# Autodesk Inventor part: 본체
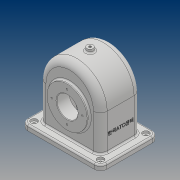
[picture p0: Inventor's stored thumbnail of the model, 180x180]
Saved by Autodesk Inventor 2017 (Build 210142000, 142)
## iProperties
Part Number: 본체
Material: 일반
Document SubType Name: Modeling
Designer: 20
Density: 1 g/cm^3
Appearance: 기본값
Author: 20
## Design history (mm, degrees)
sketch "스케치8"
  geometry: L1 (58, 0)-(58, -78); L2 (58, -78)-(-58, -78); L3 (-58, -78)-(-58, 0); A1 r 58 centre (0, 0) between (58, 0) and (-58, 0); 1 further point
  constraints: 6 end point, 2 coincident, 2 point on circle, 2 tangent, 2 vertical, 1 centre point, 1 horizontal
  dimensions: "d35" = 116 diameter of A1; "d44" = 78 distance from line of L2 point (0, 0)
extrude "돌출4" new body sketch "스케치8" stored distance "d38" = 77; taper "d39" = 0 deg
sketch "스케치11"
  geometry: L1 (-58, -78)-(58, -78) reference; C1 r 38 at (0, -13); 1 further point
  constraints: 1 centre point, 1 vertical alignment
  dimensions: "d45" = 76 diameter of C1; "d46" = 65 distance from line of L1 C1.centre
extrude "돌출5" join sketch "스케치11" distance "d47" = 5; taper "d48" = 0 deg
sketch "스케치12"
  geometry: L1 (58, 78)-(-58, 78) reference; C1 r 38 at (0, 13); 1 further point
  constraints: 1 centre point, 1 vertical alignment
  dimensions: "d49" = 76 diameter of C1; "d50" = 65 distance from line of L1 C1.centre
extrude "돌출6" join sketch "스케치12" distance "d51" = 10; taper "d52" = 0 deg
sketch "스케치14"
  geometry: L1 (52, 0)-(52, -78); L2 (-52, 0)-(-52, -78); L3 (52, -78)-(-52, -78); A1 r 52 centre (0, 0) between (52, 0) and (-52, 0); 1 further point
  constraints: 6 end point, 2 point on circle, 2 tangent, 2 vertical, 1 centre point, 1 coincident, 1 horizontal
  dimensions: "d62" = 104 diameter of A1; "d63" = 78 distance from line of L3 point (0, 0)
extrude "돌출7" cut sketch "스케치14" stored distance "d64" = 67; taper "d65" = 0 deg
node "작업 평면3"
sketch "스케치18"
  geometry: L1 (-52, -65)-(52, -65) reference; C1 r 28 at (0, 0); 1 further point
  constraints: 1 centre point, 1 vertical alignment
  dimensions: "d72" = 56 diameter of C1; "d73" = 65 distance from line of L1 C1.centre
extrude "돌출9" join sketch "스케치18" distance "d74" = 14; taper "d75" = 40 deg
sketch "스케치19"
  geometry: C1 r 38 at (0, 0) reference; C2 r 20 at (0, 0); 1 further point
  constraints: 1 centre point, 1 coincident
  dimensions: "d76" = 40 diameter of C2
extrude "돌출10" cut sketch "스케치19" stored distance "d77" = 67; taper "d78" = 0 deg
sketch "스케치20"
  geometry: L1 (-17, -93.5)-(133, -93.5); L2 (133, -93.5)-(133, 16.5); L3 (133, 16.5)-(-17, 16.5); L4 (-17, 16.5)-(-17, -93.5); L5 (-17, -93.5)-(133, 16.5); L6 (133, -93.5)-(-17, 16.5); L7 (0, 0)-(0, -77) reference; L8 (116, -77)-(0, -77) reference; L9 (116, 0)-(116, -77) reference; L10 (0, 0)-(116, 0) reference; 1 further point
  constraints: 12 end point, 2 midpoint, 2 parallel, 1 horizontal, 1 perpendicular
  dimensions: "d79" = 150 distance of L3.end L2.end; "d80" = 110 distance of L2.end L1.end
extrude "돌출11" join sketch "스케치20" distance "d81" = 10; taper "d82" = 0 deg
fillet "모깎기2" dims "d83" = 12
hole "구멍1" diameter "d86" = 5; stored, may be unused: countersink angle "d90" = 90 deg, drill point angle "d92" = 118 deg; dims "d84" = 10, "d85" = 10, "d87" = 6, "d88" = 12, "d89" = 4, "d91" = 8
hole "구멍2" diameter "d95" = 5; stored, may be unused: countersink angle "d99" = 90 deg, drill point angle "d101" = 118 deg; dims "d93" = 10, "d94" = 10, "d96" = 6, "d97" = 12, "d98" = 4, "d100" = 8
hole "구멍3" diameter "d104" = 5; stored, may be unused: countersink angle "d108" = 90 deg, drill point angle "d110" = 118 deg; dims "d102" = 10, "d103" = 10, "d105" = 6, "d106" = 12, "d107" = 4, "d109" = 8
hole "구멍4" diameter "d113" = 5; stored, may be unused: countersink angle "d117" = 90 deg, drill point angle "d119" = 118 deg; dims "d111" = 10, "d112" = 10, "d114" = 6, "d115" = 12, "d116" = 4, "d118" = 8
fillet "모깎기4" dims "d121" = 13
fillet "모깎기5" dims "d122" = 8
fillet "모깎기6" dims "d123" = 3
fillet "모깎기7" dims "d124" = 3
chamfer "모따기1" distance "d125" = 1; stored, may be unused: second distance "d126" = 2, angle "d127" = 45 deg
node "작업 평면4"
sketch "스케치22"
  geometry: L1 (138, -12)-(138, -98) reference; L2 (126, -110)-(0, -110) reference; C1 r 6 at (63, -55); 1 further point
  constraints: 1 centre point
  dimensions: "d131" = 12 diameter of C1; "d132" = 55 distance from line of L2 C1.centre; "d133" = 75 distance from line of L1 C1.centre
extrude "돌출12" join sketch "스케치22" stored distance "d134" = 10; taper "d135" = 5 deg
hole "구멍5" diameter "d138" = 4.459; stored, may be unused: countersink angle "d142" = 90 deg, drill point angle "d144" = 118 deg; dims "d136" = 10, "d137" = 10, "d139" = 10, "d140" = 12, "d141" = 4, "d143" = 12.8
sketch "스케치23"
  geometry: C1 r 38 at (0, 0) reference; 2 further points
  constraints: 1 vertical alignment
  dimensions: "d145" = 29 distance of C1.centre point (0, 29)
hole "구멍6" sketch "스케치23" at (0, 29) diameter "d146" = 3.242; stored, may be unused: countersink angle "d150" = 90 deg, drill point angle "d152" = 118 deg; dims "d147" = 8, "d148" = 12, "d149" = 4, "d151" = 10
sketch "스케치24"
  geometry: C1 r 21 at (0, 0) reference; 2 further points
  constraints: 1 vertical alignment
  dimensions: "d156" = 29 distance of C1.centre point (0, -29)
hole "구멍7" sketch "스케치24" at (0, -29) diameter "d157" = 3.242; stored, may be unused: countersink angle "d161" = 90 deg, drill point angle "d163" = 118 deg; dims "d158" = 8, "d159" = 12, "d160" = 4, "d162" = 10
fillet "모깎기8" dims "d167" = 3
sketch "스케치26"
  geometry: L1 (0, -13)-(65, -13) reference; L2 (78, -17.5)-(78, -29.5) reference; 2 further points
  constraints: 1 other
  dimensions: "d168" = 38.5 distance from line of L1 point (38, 25.5); "d169" = 40 distance from line of L2 point (38, 25.5)
feature "엠보싱1" sketch "스케치26" dims "d35" = 116, "d44" = 78, "d170" = 0.5, "d171" = 0
fillet "모깎기10" dims "d173" = 3
node "솔리드2"
pattern_circular "원형 패턴1" dims angle "d154" = 360 deg
pattern_circular "원형 패턴2" dims angle "d165" = 360 deg
other parameters: "d71" = -24, "d128" = -142
